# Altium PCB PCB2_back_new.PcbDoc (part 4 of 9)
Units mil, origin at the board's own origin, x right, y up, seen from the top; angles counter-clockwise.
Board outline 6299 x 3937 mil, 4 copper layers (TopLayer, GROUND, VCC, BottomLayer); 253 components, 421 nets, 2085 pads, 712 vias.
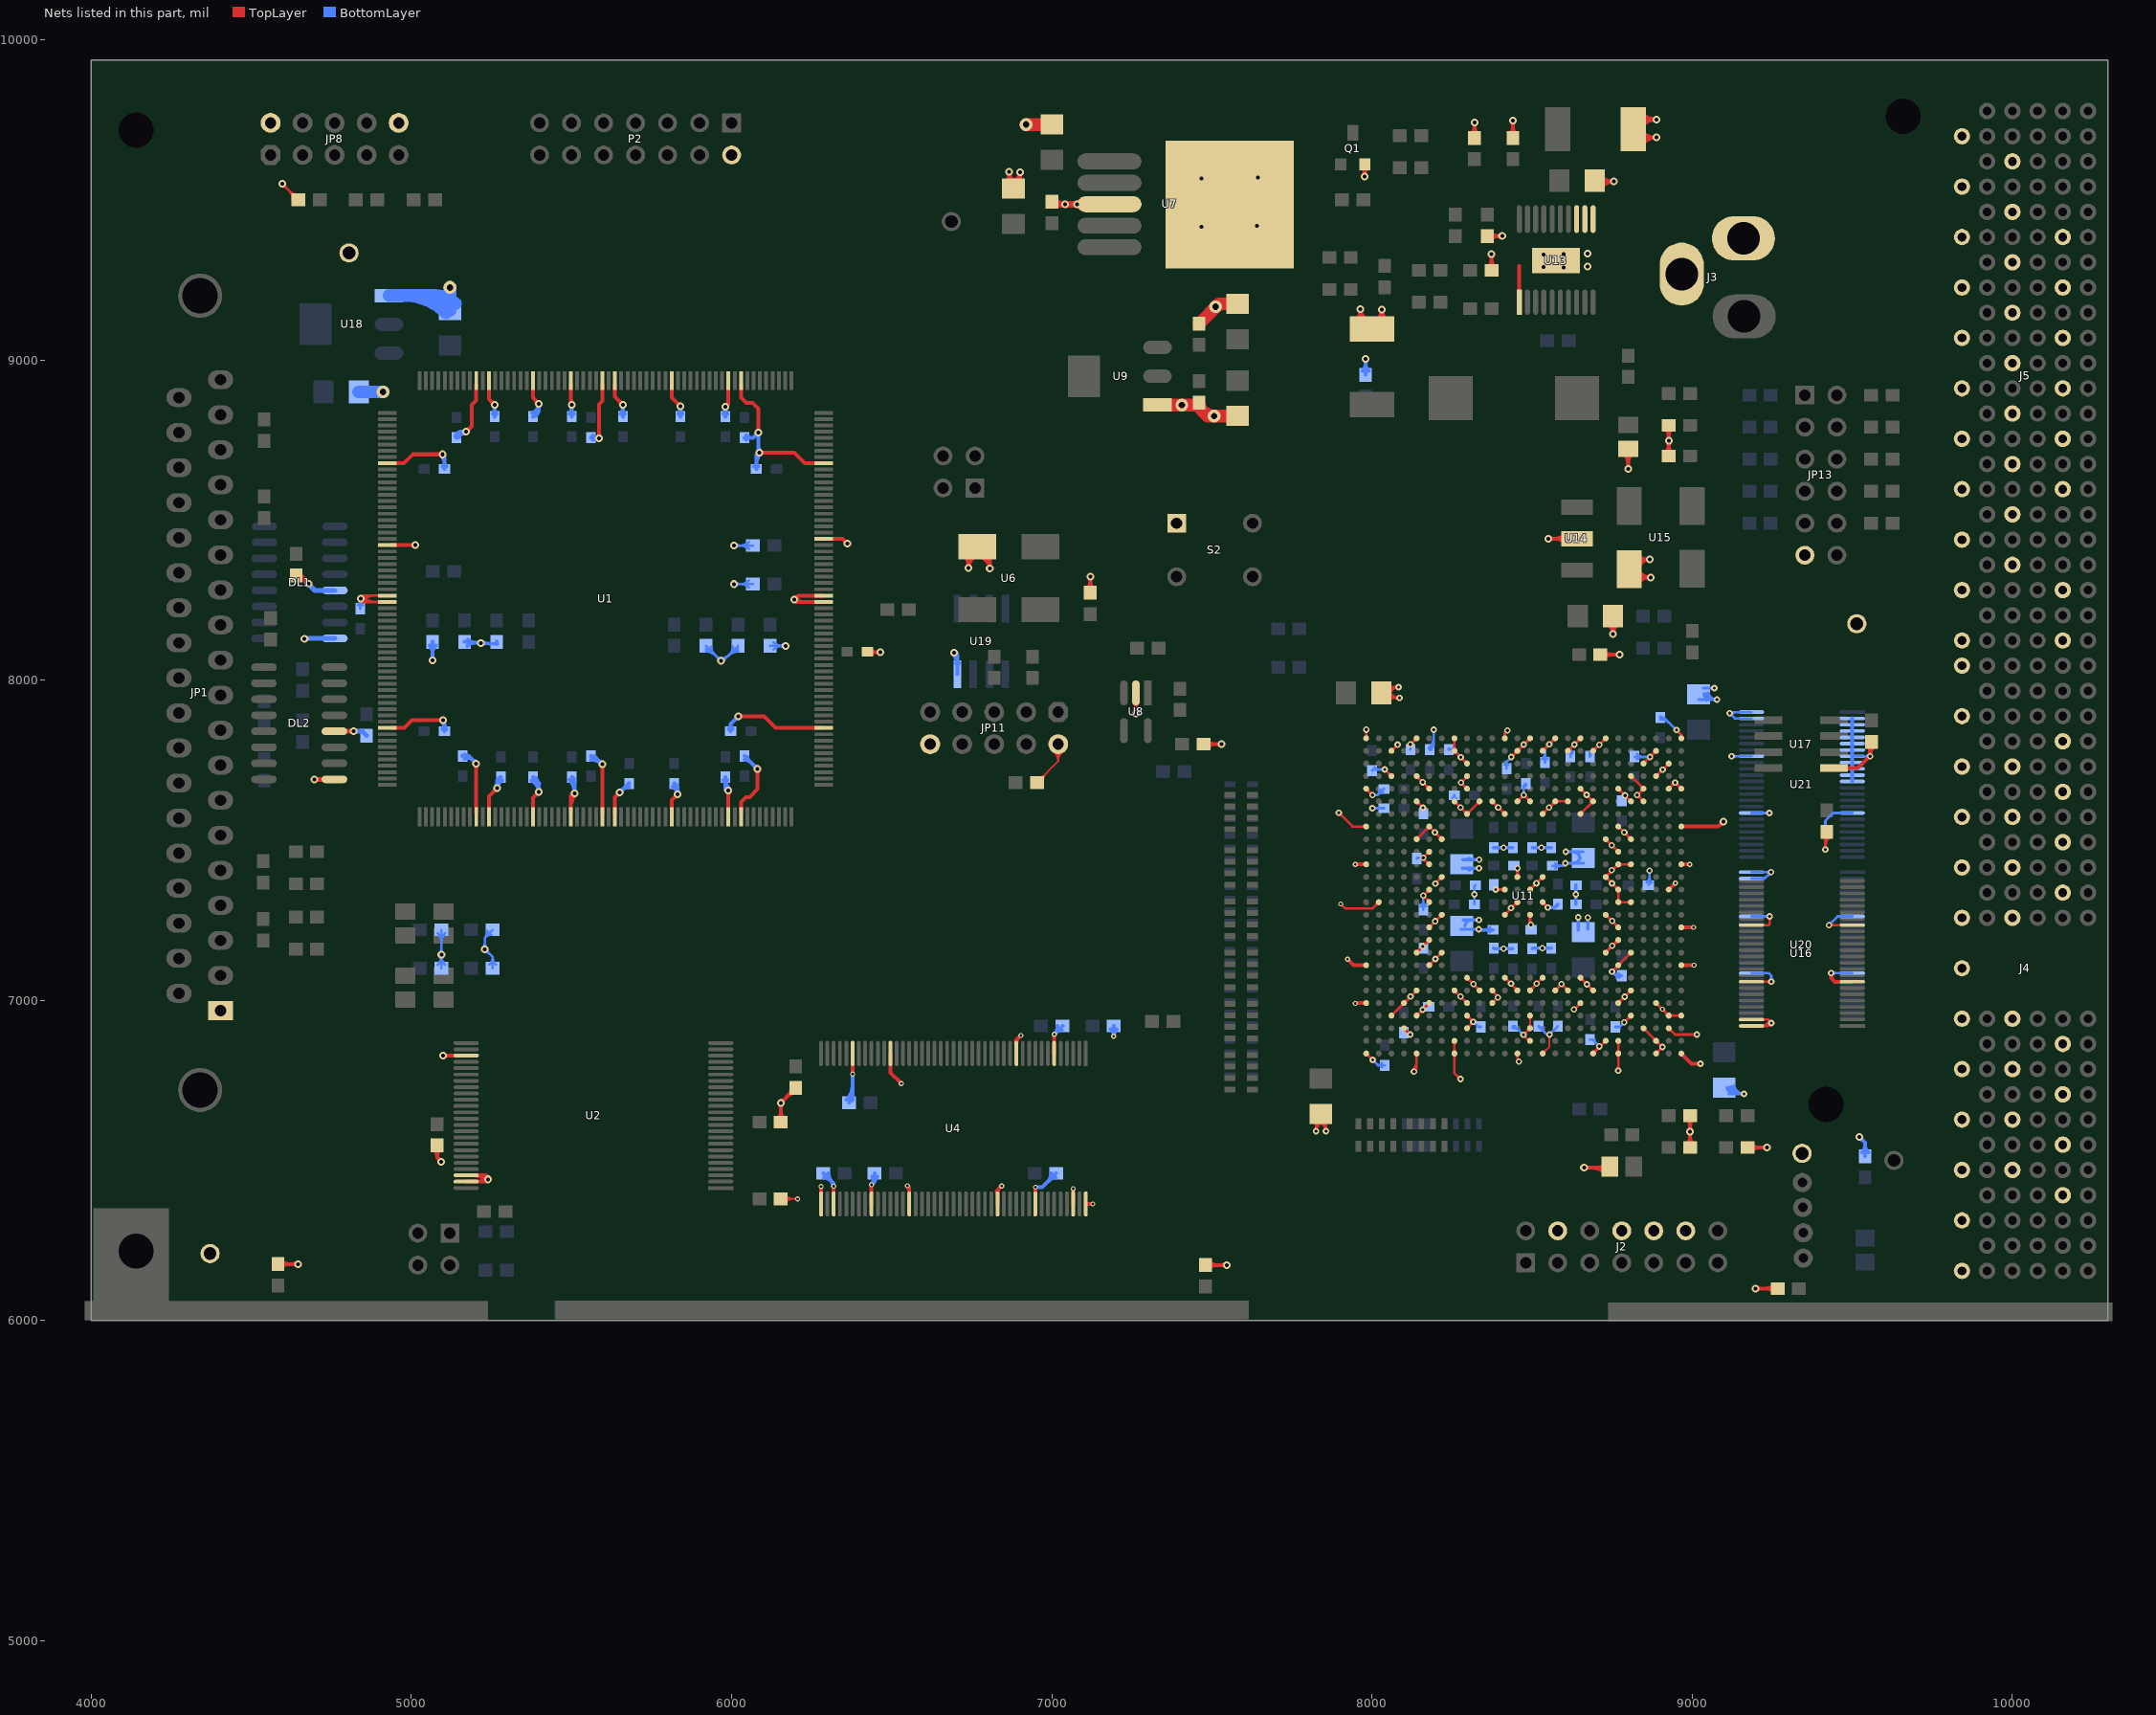
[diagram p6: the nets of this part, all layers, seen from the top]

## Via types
v1: diameter 16, hole 8, TopLayer to BottomLayer, 311 vias
v2: diameter 20, hole 10, TopLayer to BottomLayer, 202 vias
v3: diameter 24, hole 12, TopLayer to BottomLayer, 179 vias
v4: diameter 40, hole 20, TopLayer to BottomLayer, 12 vias
v5: diameter 30, hole 15, TopLayer to BottomLayer, 8 vias

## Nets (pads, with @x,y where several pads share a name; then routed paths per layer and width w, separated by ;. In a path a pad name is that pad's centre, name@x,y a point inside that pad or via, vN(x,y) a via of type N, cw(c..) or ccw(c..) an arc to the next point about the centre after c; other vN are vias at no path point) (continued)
GND: C1.2 C2.2 C5.1 C7.2 C8.1 C10.2 C12.2 C13.2 C14.2 C15.1 C16.1 C17.1 C18.1 C19.1 C20.2 C21.2 C23.2 C27.1 C28.1 C29.2 C30.2 C31.2 C32.1 C33.1 C34.1 C36.1 C37.1 C38.2 C40.2 C42.1 C43.2 C44.2 C45.2 C46.1 C47.2 C48.2 C49.2 C50.2 C51.2 C52.2 C53.2 C54.2 C56.2 C57.2 C58.2 C60.2 C61.2 C63.2 C64.2 C67.2 C68.1 C69.2 C71.2 C72.2 C73.2 C75.2 C76.1 C77.2 C79.1 C80.1 C81.1 C82.1 C83.1 C84.1 C91.2 C92.1 C93.2 C94.2 C95.2 C96.2 C97.2 C98.2 C99.2 C100.2 C101.2 C102.2 C103.2 C104.2 C105.1 C106.2 C107.2 C108.2 C109.2 C110.2 C111.2 C112.1 C113.2 C114.2 C115.2 C116.2 C119.2 C120.2 C121.2 C122.2 C123.2 C124.2 C125.2 C126.2 C127.2 C128.2 C129.2 C130.1 C131.2 C132.2 C133.2 C134.2 C135.2 C136.2 C137.2 C138.2 C139.2 C140.2 C141.2 C142.2 C143.2 C144.2 C145.2 C146.2 C147.2 C148.2 DL1.5 DL1.8 DL2.9 DL2.12 DS4.2 DS5.2 FB1.2 FB3.2 FB5.2 J2.4 J2.8 J2.10 J2.12 J3.2 J3.3 J4.B4 J4.B6 J4.B8 J4.B10 J4.B16 J4.B18 J4.B20 J4.B22 J4.D5 J4.D7 J4.D9 J4.D11 J4.D15 J4.D17 J4.D19 J4.D21 J4.F1 J4.F3 J4.F5 J4.F7 J4.F9 J4.F11 J4.F13 J4.F15 J4.F17 J4.F19 J4.F21 J4.F23 J4.F25 J5.B1 J5.B3 J5.B7 J5.B9 J5.B11 J5.B13 J5.B15 J5.B17 J5.D4 J5.D6 J5.D8 J5.D10 J5.D12 J5.D14 J5.D16 J5.D18 J5.D20 J5.F1 J5.F3 J5.F5 J5.F7 J5.F9 J5.F11 J5.F13 J5.F15 J5.F17 J5.F19 J5.F21 JP1.1 JP8.2 JP8.10 JP11.2 JP11.10 JP13.11 P2.2 pad.5 pad.6 pad.7 pad.8 Q1.3 R4.2 R14.1 R16.2 R17.2 R20.1 R25.1 R48.1 R50.1 R52.1 R53.1 R55.1 R67.1 R68.1 R88.2 R103.2 S2.1 U1.10 U1.30 U1.31 U1.40 U1.52 U1.69 U1.71 U1.80 U1.89 U1.91 U1.96 U1.102 U1.109 U1.111 U1.129 U1.142 U1.150 U1.151 U1.171 U1.190 U1.192 U1.199 U1.205 U1.210 U1.212 U1.221 U1.230 U1.232 U2.27 U2.46 U2.47 U4.6 U4.12 U4.32 U4.38 U4.44 U4.46 U4.52 U4.58 U4.72 U4.78 U4.84 U4.86 U6.2 U7.3 U8.2 U9.1 U11.A1 U11.A3 U11.A6 U11.A8 U11.A12 U11.A14 U11.A19 U11.A22 U11.A26 U11.AA4 U11.AA5 U11.AA8 U11.AA10 U11.AA11 U11.AA13 U11.AA14 U11.AA16 U11.AA17 U11.AA19 U11.AA22 U11.AB1 U11.AB2 U11.AB4 U11.AB6 U11.AB9 U11.AB18 U11.AB21 U11.AB26 U11.AC3 U11.AC5 U11.AC18 U11.AC22 U11.AC24 U11.AD2 U11.AD4 U11.AD18 U11.AE3 U11.AE8 U11.AE10 U11.AE12 U11.AE14 U11.AE19 U11.AE24 U11.AF1 U11.AF7 U11.AF9 U11.AF11 U11.AF13 U11.AF15 U11.AF19 U11.AF22 U11.AF26 U11.B3 U11.B6 U11.B7 U11.B13 U11.B19 U11.C2 U11.C4 U11.C13 U11.C18 U11.C23 U11.D1 U11.D2 U11.D5 U11.D13 U11.D18 U11.D22 U11.D24 U11.E3 U11.E6 U11.E9 U11.E16 U11.E18 U11.E21 U11.E23 U11.E26 U11.F5 U11.F8 U11.F10 U11.F11 U11.F13 U11.F14 U11.F16 U11.F17 U11.F19 U11.F22 U11.G9 U11.G12 U11.G15 U11.G18 U11.H1 U11.H6 U11.H21 U11.H26 U11.J5 U11.J7 U11.J20 U11.J22 U11.K6 U11.K21 U11.L1 U11.L6 U11.L21 U11.M7 U11.M13 U11.M15 U11.M20 U11.N5 U11.N6 U11.N12 U11.N14 U11.N21 U11.N25 U11.P2 U11.P6 U11.P13 U11.P15 U11.P21 U11.R7 U11.R12 U11.R14 U11.R20 U11.T1 U11.T5 U11.T6 U11.T21 U11.T26 U11.U6 U11.U21 U11.V5 U11.V7 U11.V20 U11.V22 U11.W1 U11.W6 U11.W21 U11.W26 U11.Y9 U11.Y12 U11.Y15 U11.Y18 U13.1 U13.11 U13.12 U13.13 U14.2 U15.2 U16.8 U16.17 U16.32 U16.41 U16.47 U16.48 U17.5 U18.1 U19.4 U20.8 U20.17 U20.32 U20.41 U20.47 U20.48 U21.2 U21.3 U21.4 U21.5 U21.6 U21.7 U21.8 U21.9 U21.10 U21.11 U21.12 U21.17 U21.32 U21.41 U21.47 U21.48 | length 33527.3
  TopLayer w6: R20.1@6153.46,6380 v1(6206,6380) ; R20.1@6162.99,6372.44 cw(c6181.23,6354.2) 6181.23,6380 cw(c6181.23,6405.8) R20.1@6162.99,6387.56 ; R20.1@6167.23,6368.2 cw(c6195.71,6339.72) 6195.71,6380 cw(c6195.71,6420.28) R20.1@6167.23,6391.8 ; v1@6202.46,6376.46 ccw(c6193.93,6367.93) 6193.93,6380 ccw(c6193.93,6392.07) v1@6202.46,6383.54 ; R25.1@6953.46,7680 7020,7746.54 ; R25.1@6955.43,7690.69 ccw(c6955.43,7711.73) R25.1@6970.31,7696.85 ; R25.1@6955.43,7696.69 ccw(c6955.43,7732.21) 6980.56,7707.09 ; R25.1@6966.12,7680 cw(c6996.67,7680) 6975.07,7701.6 ; R25.1@6972.12,7680 cw(c7017.15,7680) 6985.31,7711.84 ; JP11.2@7004.05,7776.98 cw(c6982.96,7746.54) 7020,7746.54 ; JP11.2@7007.47,7781.92 cw(c6990.9,7757.99) 7020,7757.99 cw(c7049.1,7757.99) JP11.2@7032.53,7781.92 ; JP11.2@7020,7800 7020,7746.54 ; JP11.2@7035.95,7776.98 ccw(c7057.04,7746.54) 7020,7746.54 ; U11.C13@8489.14,6917.16 ccw(c8478.47,6927.83) 8493.56,6927.83 ccw(c8508.65,6927.83) U11.C13@8497.98,6917.16 ; U11.D13@8489.14,6947.69 cw(c8478.47,6937.02) 8493.56,6937.02 cw(c8508.65,6937.02) U11.D13@8497.98,6947.69 ; U11.C13@8493.56,6912.74 U11.D13@8493.56,6952.11 ; U11.A12@8532.93,6834 8553.99,6855.06 v2(8553.99,6893) ; U11.A12@8532.93,6840.25 ccw(c8532.93,6855.35) 8543.6,6844.67 ccw(c8554.27,6834) U11.A12@8539.18,6834
  TopLayer w8: v3@4596.54,9542 cw(c4596.54,9522.69) 4610.19,9536.34 cw(c4623.85,9550) v3@4604.54,9550 ; v3(4596.54,9550) R14.1@4646.54,9500 ; 4616.4,9530.14 cw(c4586.26,9500) R14.1@4628.88,9500 ; 4621.15,9525.38 ccw(c4644.57,9548.8) R14.1@4644.57,9515.68 ; R14.1@4630.06,9516.48 cw(c4613.58,9500) R14.1@4636.88,9500 ; v3@4836.34,8249.34 ccw(c4848.86,8261.86) 4848.86,8244.16 ; v3@4843.4,8247.12 cw(c4845.28,8236.6) 4852.84,8244.16 ; v3@4844.76,8262.51 ccw(c4846.76,8267.93) 4850.84,8263.84 ; v3@4847.66,8249.34 cw(c4882.66,8214.34) 4882.66,8263.84 ; v3@4847.66,8260.66 ccw(c4887.49,8300.49) 4887.49,8244.16 ; v3@4849.51,8257.76 cw(c4854.93,8259.76) 4850.84,8263.84 ; v3@4849.88,8253.6 ccw(c4860.4,8251.72) 4852.84,8244.16 ; 4863.35,8263.84 ccw(c4863.35,8233.65) v3(4842,8255) ; 4868.18,8244.16 cw(c4868.18,8281.18) v3(4842,8255) ; U1.151@4937.69,8244.16 U1.151@4924.9,8244.16 4852.84,8244.16 ; U1.150@4937.69,8263.84 U1.150@4924.9,8263.84 4850.84,8263.84 ; C20.2@7816.62,6625.44 cw(c7796.39,6605.21) 7825,6605.21 ; v2@7820.76,6595.24 ccw(c7810.51,6605.49) 7825,6605.49 ccw(c7839.49,6605.49) v2@7829.24,6595.24 ; v2@7825,6589.88 cw(c7856.01,6589.88) C20.2@7845.44,6619.03 ; v2(7825,6591) C20.2@7825,6639 ; 7825,6601.29 cw(c7851.87,6601.29) C20.2@7842.71,6626.55 ; 7825,6612.7 cw(c7847.74,6612.7) C20.2@7839.98,6634.07 ; C20.2@7835.09,6618.85 cw(c7825.18,6589.67) v2@7856,6589.67 ; C20.2@7837.67,6626.42 cw(c7828.98,6600.83) v2@7856,6600.83 ; C20.2@7840.24,6634 cw(c7832.77,6612) 7856,6612 ; v2@7851.76,6595.24 ccw(c7841.51,6605.49) 7856,6605.49 ccw(c7870.49,6605.49) v2@7860.24,6595.24 ; v2(7856,6591) C20.2@7856,6644 ; 7856,6607.62 cw(c7881.2,6607.62) C20.2@7863.38,6625.44 ; v2@7896,7580 cw(c7896,7565.51) 7906.24,7575.76 cw(c7916.49,7586) v2@7902,7586 ; v2(7896,7586) 7939.34,7542.66 U11.W26@7981.75,7542.66 ; v1@7902,7297 cw(c7902,7287.34) 7908.83,7294.17 cw(c7915.66,7301) v1@7906,7301 ; v1(7902,7301) 7916,7287 8001.68,7287 U11.N25@8021.12,7306.44 ; U11.W26@7978.03,7538.95 ccw(c7969.07,7529.98) 7969.07,7542.66 ccw(c7969.07,7555.34) U11.W26@7978.03,7546.38 ; U11.AF26@7978.03,7821.97 ccw(c7969.07,7830.93) 7981.75,7830.93 ccw(c7994.43,7830.93) U11.AF26@7985.46,7821.97 ; U11.A26@7981.75,6828.75 cw(c7981.75,6816.07) 7990.71,6825.03 cw(c7999.68,6834) U11.A26@7987,6834 ; U11.A26@7981.75,6834 v2(8002,6813.75) ; U11.AB26@7981.75,7655.52 cw(c7981.75,7642.84) 7990.71,7651.81 cw(c7999.68,7660.77) U11.AB26@7987,7660.77 ; U11.AB26@7981.75,7660.77 v2(8001.52,7641) ; U11.AF26@7981.75,7818.25 v2(7981.75,7845.25) ; U11.N25@8015.87,7306.44 cw(c8003.19,7306.44) 8012.15,7297.48 cw(c8021.12,7288.51) U11.N25@8021.12,7301.19 ; C21.2@8025,7944 v2(8086,7944) cw(c8086,7977.18) C21.2@8054.9,7965.63 ; C21.2@8029,7978 v2(8083,7978) ccw(c8083,7949.79) C21.2@8055.71,7956.95 ; v2(8039.63,7721) U11.AC24@8060.49,7700.14 ; C21.2@8039.9,7960.06 ccw(c8062.99,7968.64) 8062.99,7944 ; C21.2@8040.24,7961.02 cw(c8062.25,7955.24) 8062.25,7978 ; C21.2@8047.4,7962.85 ccw(c8074.5,7972.91) 8074.5,7944 ; C21.2@8047.97,7958.99 cw(c8072.63,7952.51) 8072.63,7978 ; C21.2@8048.56,7936.62 cw(c8066.38,7918.8) 8066.38,7944 ; C21.2@8048.56,7983.38 ccw(c8061.55,7996.37) 8061.55,7978 ; U11.AC24@8055.24,7700.14 ccw(c8042.56,7700.14) 8051.52,7709.11 ccw(c8060.49,7718.07) U11.AC24@8060.49,7705.39 ; U11.D24@8060.49,6952.11 U11.F22@8139.23,7030.85 ; U11.D24@8060.49,6957.36 ccw(c8060.49,6970.04) 8069.45,6961.08 ccw(c8078.42,6952.11) U11.D24@8065.74,6952.11 ; U11.AE24@8060.49,7778.88 v2(8080,7798.39) ; U11.AE24@8060.49,7784.13 ccw(c8060.49,7796.81) 8069.45,7787.85 ccw(c8078.42,7778.88) U11.AE24@8065.74,7778.88 ; v2@8078.76,7973.76 ccw(c8068.51,7963.51) 8068.51,7978 ccw(c8068.51,7992.49) v2@8078.76,7982.24 ; v2@8081.76,7939.76 ccw(c8071.51,7929.51) 8071.51,7944 ccw(c8071.51,7958.49) v2@8081.76,7948.24 ; U11.E23@8094.61,6991.48 cw(c8081.93,6991.48) 8090.89,6982.51 cw(c8099.86,6973.55) U11.E23@8099.86,6986.23 ; U11.C23@8099.86,6907.49 cw(c8099.86,6894.81) 8108.82,6903.77 cw(c8117.79,6912.74) U11.C23@8105.11,6912.74 ; U11.C23@8099.86,6912.74 v2(8119.6,6893) ; U11.E23@8099.86,6996.73 ccw(c8099.86,7009.41) 8108.82,7000.45 ccw(c8117.79,6991.48) U11.E23@8105.11,6991.48 ; v2(8120,7799.02) U11.AF22@8139.23,7818.25 ; v2@8126.76,6781.24 ccw(c8096.65,6811.35) 8139.23,6811.35 ; v2(8131,6777) 8139.23,6785.23 ; v2@8132,6782.92 ccw(c8133.37,6791.08) 8139.23,6785.23 ; v2@8132.41,6775.59 ccw(c8115.96,6792.04) 8139.23,6792.04 ; U11.AF22@8133.98,7818.25 cw(c8121.3,7818.25) 8130.26,7809.29 cw(c8139.23,7800.32) U11.AF22@8139.23,7813 ; U11.A22@8135.51,6830.29 cw(c8126.55,6821.32) 8139.23,6821.32 cw(c8151.91,6821.32) U11.A22@8142.94,6830.29 ; v2@8136.92,6778 cw(c8145.08,6779.37) 8139.23,6785.23 ; U11.A22@8139.23,6834 8139.23,6785.23 ; U11.D22@8139.23,6952.11 U11.E21@8178.6,6991.48 ; U11.D22@8139.23,6957.36 ccw(c8139.23,6970.04) 8148.19,6961.08 ccw(c8157.16,6952.11) U11.D22@8144.48,6952.11 ; U11.J22@8139.23,7148.96 U11.K21@8178.6,7188.33 ; U11.J22@8139.23,7154.21 ccw(c8139.23,7166.89) 8148.19,7157.93 ccw(c8157.16,7148.96) U11.J22@8144.48,7148.96 ; U11.V22@8139.23,7503.29 U11.W21@8178.6,7542.66 U11.V20@8217.97,7503.29 ; U11.V22@8139.23,7508.54 ccw(c8139.23,7521.22) 8148.19,7512.26 ccw(c8157.16,7503.29) U11.V22@8144.48,7503.29 ; U11.AA22@8139.23,7616.15 cw(c8139.23,7603.47) 8148.19,7612.44 cw(c8157.16,7621.4) U11.AA22@8144.48,7621.4 ; U11.AA22@8139.23,7621.4 v2(8159,7601.63) ; U11.AC22@8139.23,7694.89 cw(c8139.23,7682.21) 8148.19,7691.18 cw(c8157.16,7700.14) U11.AC22@8144.48,7700.14 ; U11.AC22@8139.23,7700.14 U11.AB21@8178.6,7660.77 ; 8170,7337 cw(c8178.6,7328.4) U11.P21@8178.6,7340.56 ; 8172.98,7314.02 ccw(c8178.6,7319.64) U11.N21@8178.6,7311.69 ; U11.E21@8173.35,6991.48 cw(c8160.67,6991.48) 8169.63,6982.51 cw(c8178.6,6973.55) U11.E21@8178.6,6986.23 ; U11.K21@8173.35,7188.33 cw(c8160.67,7188.33) 8169.63,7179.37 cw(c8178.6,7170.4) U11.K21@8178.6,7183.08 ; U11.T21@8173.35,7424.55 ccw(c8160.67,7424.55) 8169.63,7433.52 ccw(c8178.6,7442.48) U11.T21@8178.6,7429.8 ; U11.U21@8173.35,7463.92 cw(c8160.67,7463.92) 8169.63,7454.96 cw(c8178.6,7445.99) U11.U21@8178.6,7458.67 ; U11.W21@8173.35,7542.66 cw(c8160.67,7542.66) 8169.63,7533.7 cw(c8178.6,7524.73) U11.W21@8178.6,7537.41 ; U11.AB21@8173.35,7660.77 ccw(c8160.67,7660.77) 8169.63,7669.74 ccw(c8178.6,7678.7) U11.AB21@8178.6,7666.02 ; U11.H21@8178.6,7109.59 U11.J20@8217.97,7148.96 ; U11.H21@8178.6,7114.84 ccw(c8178.6,7127.52) 8187.56,7118.56 ccw(c8196.53,7109.59) U11.H21@8183.85,7109.59 ; U11.L21@8178.6,7227.7 U11.M20@8217.97,7267.07 ; U11.N21@8178.6,7306.44 8178.6,7308.4 v2(8160,7327) 8178.6,7345.6 U11.P21@8178.6,7345.81 ; U11.T21@8178.6,7424.55 8159.68,7443.47 v2(8159.68,7445) U11.U21@8178.6,7463.92 ; v2(8197.79,7365) U11.R20@8217.97,7385.18 ; U11.J20@8212.72,7148.96 cw(c8200.04,7148.96) 8209,7140 cw(c8217.97,7131.03) U11.J20@8217.97,7143.71 ; U11.M20@8212.72,7267.07 cw(c8200.04,7267.07) 8209,7258.11 cw(c8217.97,7249.14) U11.M20@8217.97,7261.82 ; U11.R20@8212.72,7385.18 cw(c8200.04,7385.18) 8209,7376.22 cw(c8217.97,7367.25) U11.R20@8217.97,7379.93 ; U11.V20@8212.72,7503.29 ccw(c8200.04,7503.29) 8209,7512.26 ccw(c8217.97,7521.22) U11.V20@8217.97,7508.54 ; U11.A19@8253.62,6830.29 cw(c8244.66,6821.32) 8257.34,6821.32 cw(c8270.02,6821.32) U11.A19@8261.05,6830.29 ; U11.A19@8253.62,6837.71 ccw(c8244.66,6846.68) 8257.34,6846.68 ccw(c8270.02,6846.68) U11.A19@8261.05,6837.71 ; U11.B19@8253.62,6869.66 cw(c8244.66,6860.69) 8257.34,6860.69 cw(c8270.02,6860.69) U11.B19@8261.05,6869.66 ; U11.AE19@8253.62,7782.6 ccw(c8244.66,7791.56) 8257.34,7791.56 ccw(c8270.02,7791.56) U11.AE19@8261.05,7782.6 ; U11.AF19@8253.62,7814.54 cw(c8244.66,7805.57) 8257.34,7805.57 cw(c8270.02,7805.57) U11.AF19@8261.05,7814.54 ; U11.B19@8257.34,6873.37 8257.34,6772.66 v2(8276,6754) ; U11.F19@8257.34,7025.6 cw(c8257.34,7012.92) 8266.3,7021.88 cw(c8275.27,7030.85) U11.F19@8262.59,7030.85 ; U11.F19@8257.34,7030.85 U11.E18@8296.71,6991.48 ; U11.AA19@8257.34,7616.15 cw(c8257.34,7603.47) 8266.3,7612.44 cw(c8275.27,7621.4) U11.AA19@8262.59,7621.4 ; U11.AA19@8257.34,7621.4 U11.Y18@8296.71,7582.03 U11.AA17@8336.08,7621.4 ; U11.AE19@8257.34,7773.63 cw(c8257.34,7760.95) 8266.3,7769.92 cw(c8275.27,7778.88) U11.AE19@8262.59,7778.88 ; U11.AF19@8257.34,7818.25 U11.AE19@8257.34,7778.88 U11.AD18@8296.71,7739.51 ; v2@8270,6754 ccw(c8255.51,6754) 8265.76,6764.24 ccw(c8276,6774.49) v2@8276,6760 ; 8290.19,7692.19 cw(c8296.71,7685.67) U11.AC18@8296.71,7694.89 ; U11.E18@8291.46,6991.48 ccw(c8278.78,6991.48) 8287.74,7000.45 ccw(c8296.71,7009.41) U11.E18@8296.71,6996.73 ; U11.Y18@8291.46,7582.03 ccw(c8278.78,7582.03) 8287.74,7591 ccw(c8296.71,7599.96) 8296.71,7587.28 ccw(c8296.71,7599.96) 8305.67,7591 ccw(c8314.64,7582.03) U11.Y18@8301.96,7582.03 ; U11.AB18@8291.46,7660.77 ccw(c8278.78,7660.77) 8287.74,7669.74 ccw(c8296.71,7678.7) U11.AB18@8296.71,7666.02 ; U11.AD18@8291.46,7739.51 ccw(c8278.78,7739.51) 8287.74,7748.48 ccw(c8296.71,7757.44) U11.AD18@8296.71,7744.76 ; U11.C18@8296.71,6912.74 8316,6932.03 v2(8316,6932.82) U11.D18@8296.71,6952.11 ; U11.C18@8296.71,6917.99 ccw(c8296.71,6930.67) 8305.67,6921.71 ccw(c8314.64,6912.74) U11.C18@8301.96,6912.74 ; U11.D18@8296.71,6946.86 cw(c8296.71,6934.18) 8305.67,6943.14 cw(c8314.64,6952.11) U11.D18@8301.96,6952.11 ; U11.G18@8296.71,7064.97 cw(c8296.71,7052.29) 8305.67,7061.26 cw(c8314.64,7070.22) U11.G18@8301.96,7070.22 ; U11.G18@8296.71,7070.22 U11.F17@8336.08,7030.85 ; U11.AB18@8296.71,7660.77 8278,7679.48 v2(8278,7680) 8296.71,7698.71 U11.AC18@8296.71,7700.14 ; U11.F17@8330.83,7030.85 ccw(c8318.15,7030.85) 8327.11,7039.82 ccw(c8336.08,7048.78) U11.F17@8336.08,7036.1 ; U11.AA17@8330.83,7621.4 cw(c8318.15,7621.4) 8327.11,7612.44 cw(c8336.08,7603.47) U11.AA17@8336.08,7616.15 ; U11.E16@8375.45,6991.48 v2(8393,7009.03) 8393,7013.3 U11.F16@8375.45,7030.85 ; U11.F16@8375.45,7025.6 cw(c8375.45,7012.92) 8384.41,7021.88 cw(c8393.38,7030.85) U11.F16@8380.7,7030.85 ; U11.AA16@8375.45,7616.15 cw(c8375.45,7603.47) 8384.41,7612.44 cw(c8393.38,7621.4) U11.AA16@8380.7,7621.4 ; U11.AA16@8375.45,7621.4 U11.Y15@8414.82,7582.03 ; U11.Y15@8409.57,7582.03 ccw(c8396.89,7582.03) 8405.85,7591 ccw(c8414.82,7599.96) U11.Y15@8414.82,7587.28 ; U11.AF15@8411.1,7821.97 ccw(c8402.14,7830.93) 8414.82,7830.93 ccw(c8427.5,7830.93) U11.AF15@8418.53,7821.97 ; U11.G15@8414.82,7070.22 U11.F14@8454.19,7030.85 ; U11.M15@8414.82,7267.07 U11.N14@8454.19,7306.44 ; U11.M15@8414.82,7272.32 ccw(c8414.82,7285) 8423.78,7276.04 ccw(c8432.75,7267.07) U11.M15@8420.07,7267.07 ; U11.AF15@8414.82,7818.25 8414.82,7834.82 v2(8423,7843) ; v2(8435,7759.69) v2(8473.88,7798.58) U11.AF13@8493.56,7818.25 ; U11.F14@8448.94,7030.85 ccw(c8436.26,7030.85) 8445.22,7039.82 ccw(c8454.19,7048.78) U11.F14@8454.19,7036.1 ; U11.N14@8448.94,7306.44 cw(c8436.26,7306.44) 8445.22,7297.48 cw(c8454.19,7288.51) U11.N14@8454.19,7301.19 ; U11.AE14@8448.94,7778.88 cw(c8436.26,7778.88) 8445.22,7769.92 cw(c8454.19,7760.95) U11.AE14@8454.19,7773.63 ; U11.A14@8454.19,6834 8454.19,6813.81 v2(8459,6809) ; U11.AA14@8454.19,7621.4 v2(8473.79,7641) 8473.96,7641 U11.AA13@8493.56,7621.4 ; U11.AA14@8454.19,7626.65 ccw(c8454.19,7639.33) 8463.15,7630.37 ccw(c8472.12,7621.4) U11.AA14@8459.44,7621.4 ; U11.AE14@8454.19,7784.13 ccw(c8454.19,7796.81) 8463.15,7787.85 ccw(c8472.12,7778.88) U11.AE14@8459.44,7778.88 ; U11.C13@8488.31,6912.74 cw(c8475.63,6912.74) 8484.59,6903.77 cw(c8493.56,6894.81) U11.C13@8493.56,6907.49 ; U11.AA13@8488.31,7621.4 ccw(c8475.63,7621.4) 8484.59,7630.37 ccw(c8493.56,7639.33) U11.AA13@8493.56,7626.65 ; U11.AF13@8488.31,7818.25 cw(c8475.63,7818.25) 8484.59,7809.29 cw(c8493.56,7800.32) U11.AF13@8493.56,7813 ; U11.B13@8493.56,6873.37 8491.45,6873.37 v2(8472.82,6892) U11.C13@8493.56,6912.74 ; U11.F13@8493.56,7030.85 U11.G12@8532.93,7070.22 ; U11.F13@8493.56,7036.1 ccw(c8493.56,7048.78) 8502.52,7039.82 ccw(c8511.49,7030.85) U11.F13@8498.81,7030.85 ; U11.P13@8493.56,7345.81 U11.R12@8532.93,7385.18 ; U11.P13@8493.56,7351.06 ccw(c8493.56,7363.74) 8502.52,7354.78 ccw(c8511.49,7345.81) U11.P13@8498.81,7345.81 ; U11.R12@8527.68,7385.18 cw(c8515,7385.18) 8523.96,7376.22 cw(c8532.93,7367.25) U11.R12@8532.93,7379.93 ; U11.Y12@8532.93,7582.03 U11.AA11@8572.3,7621.4 U11.AA10@8611.67,7621.4 ; U11.Y12@8532.93,7587.28 ccw(c8532.93,7599.96) 8541.89,7591 ccw(c8550.86,7582.03) U11.Y12@8538.18,7582.03 ; U11.AE12@8532.93,7778.88 U11.AF11@8572.3,7818.25 ; U11.AE12@8532.93,7784.13 ccw(c8532.93,7796.81) 8541.89,7787.85 ccw(c8550.86,7778.88) U11.AE12@8538.18,7778.88 ; U11.AA11@8567.05,7621.4 cw(c8554.37,7621.4) 8563.33,7612.44 cw(c8572.3,7603.47) U11.AA11@8572.3,7616.15 ; U11.AF11@8567.05,7818.25 cw(c8554.37,7818.25) 8563.33,7809.29 cw(c8572.3,7800.32) U11.AF11@8572.3,7813 ; U11.F11@8572.3,7030.85 8591.52,7050.07 v2(8591.52,7051) U11.F10@8611.67,7030.85 ; U11.F11@8572.3,7036.1 ccw(c8572.3,7048.78) 8581.26,7039.82 ccw(c8590.23,7030.85) U11.F11@8577.55,7030.85 ; U11.AA11@8576.01,7617.69 cw(c8584.98,7608.72) 8584.98,7621.4 cw(c8584.98,7634.08) U11.AA11@8576.01,7625.12 ; U11.F10@8606.42,7030.85 ccw(c8593.74,7030.85) 8602.7,7039.82 ccw(c8611.67,7048.78) U11.F10@8611.67,7036.1 ; U11.AA10@8607.96,7617.69 ccw(c8598.99,7608.72) 8598.99,7621.4 ccw(c8598.99,7634.08) U11.AA10@8607.96,7625.12 ; U11.AE10@8611.67,7778.88 U11.AF9@8651.04,7818.25 ; U11.AE10@8611.67,7784.13 ccw(c8611.67,7796.81) 8620.63,7787.85 ccw(c8629.6,7778.88) U11.AE10@8616.92,7778.88 ; v2(8631,6971.44) U11.E9@8651.04,6991.48 ; U11.E9@8645.79,6991.48 cw(c8633.11,6991.48) 8642.07,6982.51 cw(c8651.04,6973.55) U11.E9@8651.04,6986.23 ; U11.AF9@8645.79,7818.25 cw(c8633.11,7818.25) 8642.07,7809.29 cw(c8651.04,7800.32) U11.AF9@8651.04,7813 ; U11.G9@8651.04,7064.97 cw(c8651.04,7052.29) 8660,7061.26 cw(c8668.97,7070.22) U11.G9@8656.29,7070.22 ; U11.G9@8651.04,7070.22 U11.F8@8690.41,7030.85 ; U11.Y9@8651.04,7582.03 U11.AA8@8690.41,7621.4 U11.AB9@8651.04,7660.77 ; U11.Y9@8651.04,7587.28 ccw(c8651.04,7599.96) 8660,7591 ccw(c8668.97,7582.03) U11.Y9@8656.29,7582.03 ; U11.AB9@8651.04,7655.52 cw(c8651.04,7642.84) 8660,7651.81 cw(c8668.97,7660.77) U11.AB9@8656.29,7660.77 ; U11.F8@8685.16,7030.85 ccw(c8672.48,7030.85) 8681.44,7039.82 ccw(c8690.41,7048.78) U11.F8@8690.41,7036.1 ; U11.A8@8690.41,6834 U11.B7@8729.78,6873.37 ; U11.A8@8690.41,6839.25 ccw(c8690.41,6851.93) 8699.37,6842.97 ccw(c8708.34,6834) U11.A8@8695.66,6834 ; U11.AA8@8690.41,7616.15 ccw(c8690.41,7603.47) 8681.44,7612.44 ccw(c8672.48,7621.4) 8685.16,7621.4 ccw(c8672.48,7621.4) 8681.44,7630.37 ccw(c8690.41,7639.33) U11.AA8@8690.41,7626.65 ; U11.AE8@8690.41,7778.88 U11.AF7@8729.78,7818.25 ; U11.AE8@8690.41,7784.13 ccw(c8690.41,7796.81) 8699.37,7787.85 ccw(c8708.34,7778.88) U11.AE8@8695.66,7778.88 ; U11.AF7@8724.53,7818.25 cw(c8711.85,7818.25) 8720.81,7809.29 cw(c8729.78,7800.32) U11.AF7@8729.78,7813 ; U11.M7@8729.78,7261.82 cw(c8729.78,7249.14) 8738.74,7258.11 cw(c8747.71,7267.07) U11.M7@8735.03,7267.07 ; U11.M7@8729.78,7267.07 U11.L6@8769.15,7227.7 ; U11.R7@8729.78,7379.93 cw(c8729.78,7367.25) 8738.75,7376.22 cw(c8747.71,7385.18) 8735.03,7385.18 cw(c8747.71,7385.18) 8738.75,7394.15 cw(c8729.78,7403.11) U11.R7@8729.78,7390.43 ; U11.V7@8729.78,7498.04 cw(c8729.78,7485.36) 8738.74,7494.33 cw(c8747.71,7503.29) U11.V7@8735.03,7503.29 ; U11.V7@8729.78,7503.29 U11.U6@8769.15,7463.92 ; U11.L6@8763.9,7227.7 ccw(c8751.22,7227.7) 8760.18,7236.67 ccw(c8769.15,7245.63) U11.L6@8769.15,7232.95 ; U11.P6@8763.9,7345.81 ccw(c8751.22,7345.81) 8760.18,7354.78 ccw(c8769.15,7363.74) U11.P6@8769.15,7351.06 ; U11.T6@8763.9,7424.55 cw(c8751.22,7424.55) 8760.18,7415.59 cw(c8769.15,7406.62) U11.T6@8769.15,7419.3 ; U11.U6@8763.9,7463.92 ccw(c8751.22,7463.92) 8760.18,7472.89 ccw(c8769.15,7481.85) U11.U6@8769.15,7469.17 ; v2@8764.76,6784.24 ccw(c8754.15,6794.85) 8769.15,6794.85 ; U11.A6@8765.44,6830.29 cw(c8756.47,6821.32) 8769.15,6821.32 cw(c8781.83,6821.32) U11.A6@8772.86,6830.29 ; U11.A6@8765.44,6837.71 ccw(c8756.47,6846.68) 8769.15,6846.68 ccw(c8781.83,6846.68) U11.A6@8772.86,6837.71 ; U11.B6@8765.44,6869.66 cw(c8756.47,6860.69) 8769.15,6860.69 cw(c8781.83,6860.69) U11.B6@8772.86,6869.66 ; U11.N6@8765.44,7310.15 ccw(c8756.47,7319.12) 8769.15,7319.12 ccw(c8781.83,7319.12) 8772.86,7310.15 ccw(c8781.83,7319.12) 8781.83,7306.44 ccw(c8781.83,7293.76) U11.N6@8772.86,7302.73 ; U11.P6@8765.44,7342.1 cw(c8756.47,7333.13) 8769.15,7333.13 cw(c8781.83,7333.13) U11.P6@8772.86,7342.1 ; v2(8769,6780) 8769.15,6780.15 U11.B6@8769.15,6873.37 ; 8769.15,6794.12 ccw(c8783.12,6794.12) v2@8773.24,6784.24 ; U11.E6@8769.15,6991.48 U11.F5@8808.52,7030.85 ; U11.E6@8769.15,6996.73 ccw(c8769.15,7009.41) 8778.12,7000.45 ccw(c8787.08,6991.48) U11.E6@8774.4,6991.48 ; U11.H6@8769.15,7109.59 U11.J5@8808.52,7148.96 ; U11.H6@8769.15,7114.84 ccw(c8769.15,7127.52) 8778.12,7118.56 ccw(c8787.08,7109.59) U11.H6@8774.4,7109.59 ; U11.W6@8769.15,7542.66 U11.V5@8808.52,7503.29 ; U11.AB6@8769.15,7655.52 cw(c8769.15,7642.84) 8778.12,7651.81 cw(c8787.08,7660.77) U11.AB6@8774.4,7660.77 ; U11.AB6@8769.15,7660.77 U11.AA5@8808.52,7621.4 ; U11.T6@8772.86,7420.84 cw(c8781.83,7411.87) 8781.83,7424.55 cw(c8781.83,7437.23) U11.T6@8772.86,7428.27 ; v2(8787.41,6931) U11.D5@8808.52,6952.11 ; U11.D5@8803.27,6952.11 cw(c8790.59,6952.11) 8799.55,6943.14 cw(c8808.52,6934.18) U11.D5@8808.52,6946.86 ; U11.F5@8803.27,7030.85 cw(c8790.59,7030.85) 8799.55,7021.88 cw(c8808.52,7012.92) U11.F5@8808.52,7025.6 ; U11.J5@8803.27,7148.96 cw(c8790.59,7148.96) 8799.55,7140 cw(c8808.52,7131.03) U11.J5@8808.52,7143.71 ; U11.V5@8803.27,7503.29 ccw(c8790.59,7503.29) 8799.55,7512.26 ccw(c8808.52,7521.22) U11.V5@8808.52,7508.54 ; U11.N5@8804.81,7302.73 ccw(c8795.84,7293.76) 8795.84,7306.44 ccw(c8795.84,7319.12) U11.N5@8804.81,7310.15 ; U11.T5@8804.81,7420.84 ccw(c8795.84,7411.87) 8795.84,7424.55 ccw(c8795.84,7437.23) U11.T5@8804.81,7428.27 ; U11.N5@8808.52,7306.44 U11.N6@8769.15,7306.44 U11.P6@8769.15,7345.81 U11.R7@8729.78,7385.18 U11.T6@8769.15,7424.55 U11.T5@8808.52,7424.55 ; U11.AC5@8808.52,7694.89 cw(c8808.52,7682.21) 8817.49,7691.18 cw(c8826.45,7700.14) U11.AC5@8813.77,7700.14 ; U11.AC5@8808.52,7700.14 U11.AB4@8847.89,7660.77 v2(8828.12,7641) 8828,7641 8847.6,7621.4 U11.AA4@8847.89,7621.4 ; 8838.43,7630.57 ccw(c8847.89,7640.04) U11.AA4@8847.89,7626.65 ; 8839.13,7629.87 cw(c8830.66,7621.4) U11.AA4@8842.64,7621.4 ; U11.C4@8847.89,6907.49 cw(c8847.89,6894.81) 8856.86,6903.77 cw(c8865.82,6912.74) U11.C4@8853.14,6912.74 ; U11.C4@8847.89,6912.74 8906.63,6854 v2(8907.26,6854) U11.A3@8887.26,6834 ; U11.AB4@8847.89,7655.52 ccw(c8847.89,7642.84) 8838.92,7651.81 ccw(c8829.96,7660.77) 8842.64,7660.77 ccw(c8829.96,7660.77) 8838.92,7669.74 ccw(c8847.89,7678.7) U11.AB4@8847.89,7666.02 ; U11.AD4@8847.89,7739.51 U11.AE3@8887.26,7778.88 ; U11.AD4@8847.89,7744.76 ccw(c8847.89,7757.44) 8856.86,7748.48 ccw(c8865.82,7739.51) U11.AD4@8853.14,7739.51 ; U11.B3@8882.01,6873.37 ccw(c8869.33,6873.37) 8878.29,6882.34 ccw(c8887.26,6891.3) U11.B3@8887.26,6878.62 ; U11.AE3@8882.01,7778.88 cw(c8869.33,7778.88) 8878.29,7769.92 cw(c8887.26,7760.95) U11.AE3@8887.26,7773.63 ; U11.A3@8887.26,6839.25 ccw(c8887.26,6851.93) 8896.23,6842.97 ccw(c8905.19,6834) U11.A3@8892.51,6834 ; U11.B3@8887.26,6868.12 cw(c8887.26,6855.44) 8896.23,6864.4 cw(c8905.19,6873.37) U11.B3@8892.51,6873.37 ; U11.E3@8887.26,6986.23 cw(c8887.26,6973.55) 8896.23,6982.51 cw(c8905.19,6991.48) U11.E3@8892.51,6991.48 ; U11.E3@8887.26,6991.48 U11.D2@8926.63,6952.11 U11.D1@8966,6952.11 ; U11.AC3@8887.26,7700.14 U11.AD2@8926.63,7739.51 ; U11.AC3@8887.26,7705.39 ccw(c8887.26,7718.07) 8896.23,7709.11 ccw(c8905.19,7700.14) U11.AC3@8892.51,7700.14 ; U11.D2@8921.38,6952.11 ccw(c8908.7,6952.11) 8917.66,6961.08 ccw(c8926.63,6970.04) U11.D2@8926.63,6957.36 ; U11.C2@8926.63,6907.49 cw(c8926.63,6894.81) 8935.6,6903.77 cw(c8944.56,6912.74) U11.C2@8931.88,6912.74 ; U11.C2@8926.63,6912.74 8946.37,6893 v2(9015,6893) ; U11.AB2@8926.63,7660.77 8945.86,7680 v2(8946.77,7680) U11.AB1@8966,7660.77 ; U11.AB2@8926.63,7666.02 ccw(c8926.63,7678.7) 8935.6,7669.74 ccw(c8944.56,7660.77) U11.AB2@8931.88,7660.77 ; U11.D2@8930.34,6948.4 cw(c8939.31,6939.43) 8939.31,6952.11 cw(c8939.31,6964.79) U11.D2@8930.34,6955.82 ; v2(8951,7844) 8966,7829 ; U11.AB1@8960.75,7660.77 ccw(c8948.07,7660.77) 8957.03,7669.74 ccw(c8966,7678.7) U11.AB1@8966,7666.02 ; U11.D1@8962.29,6948.4 ccw(c8953.32,6939.43) 8953.32,6952.11 ccw(c8953.32,6964.79) U11.D1@8962.29,6955.82 ; U11.AF1@8962.77,7822.4 ccw(c8957.63,7829) 8966,7829 ; 8963.09,7831.91 cw(c8949.44,7818.25) U11.AF1@8968.75,7818.25 ; U11.AF1@8966,7818.25 8966,7829 ; U11.AF1@8969.23,7822.4 cw(c8974.37,7829) 8966,7829 ; v2@9010.76,6888.76 ccw(c9000.51,6878.51) 9000.51,6893 ccw(c9000.51,6907.49) v2@9010.76,6897.24 ; U16.48@9185.04,6920 9238,6920 ; U16.47@9185.04,6939.69 9236.32,6939.69 v2(9247,6929) 9238,6920 ; U16.41@9185.04,7057.8 v2(9247.2,7057.8) ; U16.32@9185.04,7234.96 9238.96,7234.96 9242.2,7238.2 v2(9242.2,7262.2) ; U16.48@9210.79,6920 ccw(c9210.79,6965.21) v2@9242.76,6933.24 ; 9230.1,6920 ccw(c9230.1,6945.9) v2@9248.41,6927.59 ; v2@9237.96,7257.96 cw(c9227.72,7247.72) 9242.2,7247.72 cw(c9256.69,7247.72) v2@9246.45,7257.96 ; v2@9241,6929 ccw(c9226.51,6929) 9236.76,6939.24 ccw(c9247,6949.49) v2@9247,6935 ; v2@9241.03,6928.43 cw(c9230.58,6927.42) 9238,6920 ; v2@9242.96,7053.55 ccw(c9232.72,7043.31) 9232.72,7057.8 ccw(c9232.72,7072.28) v2@9242.96,7062.04 ; v2@9246.43,6923.03 ccw(c9245.42,6912.58) 9238,6920 ; C36.1@9408.91,7513.48 cw(c9391.79,7496.36) 9416,7496.36 cw(c9448.21,7496.36) C36.1@9425.43,7519.13 ; v2@9411.76,7475.24 ccw(c9401.51,7485.49) 9416,7485.49 ccw(c9430.49,7485.49) v2@9420.24,7475.24 ; v2(9416,7471) 9416,7522.54 C36.1@9420,7526.54 ; v2@9416,7477.04 cw(c9467.52,7477.04) C36.1@9431.09,7513.48 ; v2(9427.04,7234.96) U16.17@9500,7234.96 ; v2@9431.28,7230.72 cw(c9441.53,7220.47) 9441.53,7234.96 cw(c9441.53,7249.45) v2@9431.28,7239.2 ; v3(4842,8255) 4852.84,8244.16 ; v3(4842,8255) 4850.84,8263.84
  TopLayer w10: v2(8386.19,7345.81) U11.P15@8414.82,7345.81 ; U11.P15@8411.81,7342.8 ccw(c8404.55,7335.55) 8404.55,7345.81 ccw(c8404.55,7356.08) U11.P15@8411.81,7348.82 ; U11.R14@8451.18,7388.19 ccw(c8443.92,7395.45) 8454.19,7395.45 ccw(c8464.45,7395.45) U11.R14@8457.2,7388.19 ; U11.R14@8454.19,7385.18 v2(8454.19,7412.19) ; U11.M13@8490.55,7264.06 cw(c8483.29,7256.81) 8493.56,7256.81 cw(c8503.82,7256.81) U11.M13@8496.57,7264.06 ; U11.M13@8493.56,7267.07 8493.56,7238.44 v2(8496,7236) ; U11.N12@8532.93,7306.44 v2(8549.37,7290) ; U11.J7@8729.78,7148.96 U11.K6@8769.15,7188.33 ; U11.J7@8729.78,7153.21 ccw(c8729.78,7163.48) 8737.04,7156.22 ccw(c8744.3,7148.96) U11.J7@8734.03,7148.96 ; v2(8749.56,7090) U11.H6@8769.15,7109.59 ; U11.H6@8764.9,7109.59 cw(c8754.63,7109.59) 8761.89,7102.33 cw(c8769.15,7095.07) U11.H6@8769.15,7105.34 ; U11.K6@8764.9,7188.33 cw(c8754.63,7188.33) 8761.89,7181.07 cw(c8769.15,7173.81) U11.K6@8769.15,7184.08
  TopLayer w12: FB1.2@4583,6176.46 v3(4645.46,6176.46) ; FB1.2@4592.68,6166.79 cw(c4616.04,6143.43) 4616.04,6176.46 cw(c4616.04,6209.5) FB1.2@4592.68,6186.14 ; v3@4641.22,6172.22 ccw(c4630.98,6161.98) 4630.98,6176.46 ccw(c4630.98,6190.95) v3@4641.22,6180.71 ; U1.171@4937.69,7850.46 4977.46,7850.46 5002,7875 v3(5099,7875) ; U1.142@4937.69,8421.32 v3(5012.32,8421.32) ; U1.129@4937.69,8677.23 4976.23,8677.23 5004,8705 v3(5097,8705) ; v3@5008.08,8417.08 ccw(c4997.84,8406.84) 4997.84,8421.32 ccw(c4997.84,8435.81) v3@5008.08,8425.57 ; C5.1@5070.32,6534.89 cw(c5046.96,6511.53) 5080,6511.53 cw(c5113.04,6511.53) C5.1@5089.68,6534.89 ; C5.1@5080,6546.54 5080,6509 v3(5093,6496) ; v3@5087,6496 ccw(c5072.51,6496) 5082.76,6506.24 ccw(c5093,6516.49) v3@5093,6502 ; v3@5092.76,8700.76 ccw(c5082.51,8690.51) 5082.51,8705 ccw(c5082.51,8719.49) v3@5092.76,8709.24 ; v3@5094.76,7870.76 ccw(c5084.51,7860.51) 5084.51,7875 ccw(c5084.51,7889.49) v3@5094.76,7879.24 ; v3(5098,6827) U2.27@5170.72,6827.39 ; v3@5102.22,6831.27 ccw(c5112.41,6841.56) 5112.49,6827.08 ccw(c5112.56,6812.59) v3@5102.27,6822.78 ; U2.47@5170.72,6433.69 5231.69,6433.69 v3(5239,6441) 5226.63,6453.37 U2.46@5170.72,6453.37 ; v3(5171,8776) 5188,8793 5188,8859 5202.46,8873.46 U1.111@5202.46,8922.31 ; v3@5171,8782 ccw(c5171,8796.49) 5181.24,8786.24 ccw(c5191.49,8776) v3@5177,8776 ; U2.46@5194.65,6453.37 cw(c5194.65,6396.65) v3@5234.76,6436.76 ; v3@5198.21,7735.3 cw(c5187.97,7725.06) 5202.46,7725.06 cw(c5216.94,7725.06) v3@5206.7,7735.3 ; U1.190@5202.46,7585.69 v3(5202.46,7739.54) ; U2.47@5206.85,6433.69 ccw(c5206.85,6473.15) v3@5234.76,6445.24 ; 5223.62,6453.37 cw(c5223.62,6425.62) v3@5243.24,6445.24 ; v3@5233,6441 ccw(c5218.51,6441) 5228.76,6451.24 ccw(c5239,6461.49) v3@5239,6447 ; U1.192@5241.83,7585.69 5241.83,7637.83 v3(5267,7663) ; U1.109@5241.83,8922.31 5241.83,8877.17 v3(5260,8859) ; v3@5254,8859 ccw(c5239.51,8859) 5249.76,8869.24 ccw(c5260,8879.49) v3@5260,8865 ; v3@5261,7663 cw(c5246.51,7663) 5256.76,7652.76 cw(c5267,7642.51) v3@5267,7657 ; U1.199@5379.62,7585.69 5379.62,7632.62 v3(5398,7651) ; U1.102@5379.62,8922.31 5379.62,8881.38 v3@5398,8863 ; 5385.34,8875.66 cw(c5371.69,8862) v3@5391,8862 ; v3@5392,7651 cw(c5377.51,7651) 5387.76,7640.76 cw(c5398,7630.51) v3@5398,7645 ; U1.205@5497.73,7585.69 5497.73,7634.73 v3(5509,7646) ; 5497.73,7604.31 cw(c5550.69,7604.31) v3@5513.24,7641.76 ; 5497.73,7633.28 cw(c5521.72,7633.28) v3@5504.76,7650.24 ; 5497.73,8879.96 ccw(c5519.96,8879.96) v3@5504.24,8864.24 ; U1.96@5497.73,8922.31 5497.73,8862.27 v3(5500,8860) ; v3@5503,7646 cw(c5488.51,7646) 5498.76,7635.76 cw(c5509,7625.51) v3@5509,7640 ; v3@5581.76,8759.24 ccw(c5571.51,8769.49) 5586,8769.49 ccw(c5600.49,8769.49) v3@5590.24,8759.24 ; v3(5586,8755) 5586,8861 5596.16,8871.16 U1.91@5596.16,8922.31 ; v3@5591.91,7732.6 cw(c5581.67,7722.36) 5596.16,7722.36 cw(c5610.64,7722.36) v3@5600.4,7732.6 ; U1.210@5596.16,7585.69 v3(5596.16,7736.84) ; U1.212@5635.53,7585.69 5635.53,7634.53 v3(5650,7649) ; U1.89@5635.53,8922.31 5635.53,8884.47 v3(5660,8860) ; v3@5644,7649 cw(c5629.51,7649) 5639.76,7638.76 cw(c5650,7628.51) v3@5650,7643 ; v3@5654,8860 ccw(c5639.51,8860) 5649.76,8870.24 ccw(c5660,8880.49) v3@5660,8866 ; U1.221@5812.69,7585.69 5812.69,7624.69 v3(5831,7643) ; U1.80@5812.69,8922.31 5812.69,8882.31 v3(5840,8855) ; v3@5825,7643 cw(c5810.51,7643) 5820.76,7632.76 cw(c5831,7622.51) v3@5831,7637 ; v3@5834,8855 ccw(c5819.51,8855) 5829.76,8865.24 ccw(c5840,8875.49) v3@5840,8861 ; v3(5980,8854) 5989.86,8863.86 ; v3@5980.16,8860 ccw(c5980.53,8873.19) 5989.86,8863.86 ; v3@5985.62,7650.9 cw(c5975.37,7640.66) 5989.86,7640.66 cw(c6004.34,7640.66) v3@5994.1,7650.9 ; v3@5986,8854.16 cw(c5999.19,8854.53) 5989.86,8863.86 ; U1.230@5989.86,7585.69 v3(5989.86,7655.14) ; U1.71@5989.86,8922.31 5989.86,8863.86 ; v3(6021,7887) 6101,7887 6137.54,7850.46 U1.10@6287.1,7850.46 ; v3@6025.24,7882.76 cw(c6035.49,7872.51) 6035.49,7887 cw(c6035.49,7901.49) v3@6025.24,7891.24 ; U1.232@6029.23,7585.69 6029.23,7619.23 6045,7635 6057,7635 6081,7659 v3(6081,7721.99) ; U1.69@6029.23,8922.31 6029.23,8882.77 6046,8866 6065,8866 6083,8848 v3(6083,8773) ; v3@6076.76,7717.75 cw(c6066.51,7707.51) 6081,7707.51 cw(c6095.49,7707.51) v3@6085.24,7717.75 ; v3@6078.76,8777.24 ccw(c6068.51,8787.49) 6083,8787.49 ccw(c6097.49,8787.49) v3@6087.24,8777.24 ; v3(6086,8710) 6196,8710 6228.77,8677.23 U1.52@6274.31,8677.23 ; v3@6090.24,8705.76 cw(c6100.49,8695.51) 6100.49,8710 cw(c6100.49,8724.49) v3@6090.24,8714.24 ; C7.2@6143.79,6629.68 ccw(c6120.43,6653.04) 6153.46,6653.04 ccw(c6186.5,6653.04) C7.2@6163.14,6629.68 ; v3@6149.22,6675.76 cw(c6138.98,6665.51) 6153.46,6665.51 cw(c6167.95,6665.51) v3@6157.71,6675.76 ; C7.2@6153.46,6620 v3(6153.46,6680) C8.1@6200,6726.54 ; v3@6153.46,6686 ccw(c6153.46,6700.49) 6163.71,6690.24 ccw(c6173.95,6680) v3@6159.46,6680 ; 6173.28,6699.81 cw(c6200,6673.09) C8.1@6200,6710.88 ; 6178.03,6704.57 ccw(c6158.03,6724.57) C8.1@6186.32,6724.57 ; v3@6196,8257 ccw(c6196,8271.49) 6206.24,8261.24 ccw(c6216.49,8251) v3@6202,8251 ; v3@6200.24,8255.24 ccw(c6227,8282) 6227,8244.16 ; U1.30@6274.31,8244.16 6202.84,8244.16 v3(6196,8251) 6208.84,8263.84 U1.31@6287.1,8263.84 ; U1.40@6274.31,8441.01 6345.99,8441.01 v3(6361,8426) ; U4.44@6279.23,6364 v1(6279.23,6418.23) ; U4.46@6318.6,6364 v1(6318.6,6419.4) ; v3@6355,8426 ccw(c6340.51,8426) 6350.76,8436.24 ccw(c6361,8446.49) v3@6361,8432 ; v1(6377.65,6769.35) U4.38@6377.65,6834 ; C10.2@6422,8087.01 v3(6463.99,8087.01) ; C10.2@6432.86,8081.64 cw(c6445.83,8068.67) 6445.83,8087.01 ; C10.2@6432.86,8094.36 ccw(c6450.61,8112.12) 6450.61,8087.01 ; U4.52@6436.71,6364 v1(6436.71,6423.71) ; v3@6459.75,8082.77 ccw(c6449.51,8072.52) 6449.51,8087.01 ccw(c6449.51,8101.49) v3@6459.75,8091.25 ; U4.32@6495.77,6834 6495.77,6774.23 v1(6530,6740) ; v1@6547.59,6419.59 cw(c6530.12,6402.12) U4.58@6554.82,6402.12 ; v1@6548.9,6419 cw(c6548.58,6412.77) 6554.82,6412.77 ; v1(6549,6421) 6554.82,6415.18 U4.58@6554.82,6364 ; U6.2@6723.72,8393.25 cw(c6684.41,8353.95) v3@6740,8353.95 ; v3@6735.76,8354.24 ccw(c6725.51,8364.49) 6740,8364.49 ccw(c6754.49,8364.49) v3@6744.24,8354.24 ; v3@6740,8349.6 cw(c6782.55,8349.6) U6.2@6762.8,8387.29 ; v3(6740,8350) U6.2@6740,8416 ; 6740,8369.44 cw(c6772.16,8369.44) U6.2@6757.23,8397.92 ; U6.2@6776.8,8384.98 cw(c6764.5,8345.34) v3@6806,8345.34 ; U6.2@6780.35,8396.44 cw(c6769.55,8361.63) 6806,8361.63 ; U6.2@6783.91,8407.9 cw(c6774.61,8377.92) U6.2@6806,8377.92 ; v3@6801.76,8352.24 ccw(c6791.51,8362.49) 6806,8362.49 ccw(c6820.49,8362.49) v3@6810.24,8352.24 ; v3(6806,8348) U6.2@6806,8409 ; U4.72@6830.32,6397.46 cw(c6854.1,6397.46) 6837.28,6414.28 ; U4.72@6830.34,6397.4 cw(c6835.45,6402.37) 6830.41,6407.41 ; U4.72@6830.41,6364 6830.41,6407.41 ; v1(6843,6420) 6830.41,6407.41 ; C12.2@6858.03,9553.15 ccw(c6838.8,9572.38) 6866,9572.38 ; v3@6861.76,9582.76 cw(c6851.51,9572.51) 6866,9572.51 cw(c6880.49,9572.51) v3@6870.24,9582.76 ; C12.2@6866,9536 v3(6866,9587) ccw(c6896.13,9587) C12.2@6885.26,9558.9 ; 6866,9569.49 ccw(c6889.36,9569.49) C12.2@6880.93,9547.71 ; C12.2@6879.43,9560.21 ccw(c6874.8,9586) v3(6901,9586) C12.2@6901,9531 ; C12.2@6881.55,9548.4 ccw(c6877.38,9571.65) 6901,9571.65 ; U4.12@6889.37,6867.46 cw(c6910.87,6867.46) 6895.67,6882.67 ; U4.12@6889.4,6867.4 cw(c6894.03,6871.9) 6889.46,6876.46 ; U4.12@6889.47,6834 6889.47,6876.47 ; v3@6896.76,9581.76 cw(c6886.51,9571.51) 6901,9571.51 cw(c6915.49,9571.51) v3@6905.24,9581.76 ; v1(6903,6890) 6889.47,6876.47 ; U4.78@6948.52,6364 v1(6948.52,6416.52) ; U4.6@7007.57,6834 v1(7007.57,6894.11) ; U4.84@7066.63,6364 v1(7066.63,6411.63) ; U4.86@7106,6364 v1(7128,6364) ; C16.1@7110.32,8285.11 ccw(c7086.96,8308.47) 7120,8308.47 ccw(c7153.04,8308.47) C16.1@7129.68,8285.11 ; v3@7115.76,8318.76 cw(c7105.51,8308.51) 7120,8308.51 cw(c7134.49,8308.51) v3@7124.24,8318.76 ; C16.1@7120,8273.46 v3(7120,8323) ; v3@7258.36,7899.64 ccw(c7248.11,7909.89) 7262.6,7909.89 ccw(c7277.08,7909.89) v3@7266.84,7899.64 ; U8.2@7258.49,7928.33 cw(c7248.57,7918.41) 7262.6,7918.41 cw(c7276.63,7918.41) U8.2@7266.71,7928.33 ; v3(7262.6,7895.4) U8.2@7262.6,7960 ; C19.1@7473.46,7800 v3(7530,7800) ; FB3.2@7480,6173.46 v3(7546.46,6173.46) ; C19.1@7485.11,7790.32 cw(c7508.47,7766.96) 7508.47,7800 cw(c7508.47,7833.04) C19.1@7485.11,7809.68 ; FB3.2@7489.68,6163.79 cw(c7513.04,6140.43) 7513.04,6173.46 cw(c7513.04,6206.5) FB3.2@7489.68,6183.14 ; v3@7525.76,7795.76 ccw(c7515.51,7785.51) 7515.51,7800 ccw(c7515.51,7814.49) v3@7525.76,7804.24 ; v3@7542.22,6169.22 ccw(c7531.98,6158.98) 7531.98,6173.46 ccw(c7531.98,6187.95) v3@7542.22,6177.71 ; v1(7924,7128) 7942.41,7109.59 U11.H26@7981.75,7109.59 ; v1(7947.45,7424.55) U11.T26@7981.75,7424.55 ; C23.2@7947.45,9120.38 ccw(c7910.66,9159) v3(7964,9159) ; v1(7948,6990) 7949.48,6991.48 U11.E26@7981.75,6991.48 ; v3@7959.76,9154.76 cw(c7949.51,9144.51) 7964,9144.51 cw(c7978.49,9144.51) v3@7968.24,9154.76 ; C23.2@7964,9097 v3(7964,9159) ; 7964,9140.09 ccw(c7991.11,9140.09) C23.2@7979.57,9115.56 ; Q1.3@7969.12,9601.52 cw(c7949.12,9581.52) 7977.4,9581.52 cw(c8005.69,9581.52) Q1.3@7985.69,9601.52 ; v3@7973.16,9576.84 ccw(c7962.92,9587.08) 7977.4,9587.08 ccw(c7991.89,9587.08) v3@7981.64,9576.84 ; v3(7977.4,9572.6) Q1.3@7977.4,9610.79 ; C23.2@7984.68,9126.42 cw(c8000.01,9159) v3(7964,9159) ; C23.2@8012.67,9125.02 ccw(c7993.94,9157) v3(8031,9157) ; C23.2@8018.73,9114.66 ccw(c8006.2,9136.07) 8031,9136.07 ; v3@8026.76,9152.76 cw(c8016.51,9142.51) 8031,9142.51 cw(c8045.49,9142.51) v3@8035.24,9152.76 ; C23.2@8031,9101 v3(8031,9157) ; C23.2@8048.48,9123.68 cw(c8071.48,9157) v3(8031,9157) ; C27.1@8310.32,9705.11 ccw(c8286.96,9728.47) 8320,9728.47 ccw(c8353.04,9728.47) C27.1@8329.68,9705.11 ; v3@8315.76,9737.76 cw(c8305.51,9727.51) 8320,9727.51 cw(c8334.49,9727.51) v3@8324.24,9737.76 ; C27.1@8320,9693.46 v3(8320,9742) ; R50.1@8360,9386.54 v3(8406.46,9386.54) ; R48.1@8363.79,9289.68 ccw(c8340.43,9313.04) 8373.46,9313.04 ccw(c8406.5,9313.04) R48.1@8383.14,9289.68 ; v3@8369.22,9326.22 cw(c8358.98,9315.98) 8373.46,9315.98 cw(c8387.95,9315.98) v3@8377.71,9326.22 ; R50.1@8369.68,9376.86 cw(c8393.04,9353.5) 8393.04,9386.54 cw(c8393.04,9419.57) R50.1@8369.68,9396.21 ; R48.1@8373.46,9280 v3(8373.46,9330.46) ; v3@8402.22,9382.29 ccw(c8391.98,9372.05) 8391.98,9386.54 ccw(c8391.98,9401.02) v3@8402.22,9390.78 ; C28.1@8430.32,9705.11 ccw(c8406.96,9728.47) 8440,9728.47 ccw(c8473.04,9728.47) C28.1@8449.68,9705.11 ; v3@8435.76,9742.76 cw(c8425.51,9732.51) 8440,9732.51 cw(c8454.49,9732.51) v3@8444.24,9742.76 ; C28.1@8440,9693.46 v3(8440,9747) ; U13.1@8460,9180 8460,9293 ; v3(8550.57,8441.57) U14.2@8640,8441.57 ; v3@8554.82,8437.33 cw(c8565.06,8427.09) 8565.06,8441.57 cw(c8565.06,8456.06) v3@8554.82,8445.82 ; U14.2@8601.95,8429.11 ccw(c8571.87,8399.03) 8571.87,8441.57 ccw(c8571.87,8484.12) U14.2@8601.95,8454.04 ; v3(8662,6477) DS4.2@8743.6,6478 ; v3@8666.19,6481.29 ccw(c8676.31,6491.66) 8676.48,6477.18 ccw(c8676.66,6462.69) v3@8666.29,6472.81 ; 8685.86,6477.29 cw(c8686.6,6416.71) DS4.2@8728.92,6460.07 ; C30.2@8695,9557 v3(8756,9557) ccw(c8756,9499.17) C30.2@8713.75,9538.66 ; 8704.66,6477.52 ccw(c8704.24,6511.52) DS4.2@8728.58,6487.78 ; C30.2@8704.98,9546.85 cw(c8728.36,9525) 8728.36,9557 ; C30.2@8713.15,9574.09 ccw(c8754.41,9615.35) v3@8754.41,9557 ; C32.1@8713.46,8080 v3(8774,8080) ; 8714.83,6477.65 cw(c8715.22,6446.03) DS4.2@8737.3,6468.66 ; C32.1@8725.11,8070.32 cw(c8748.47,8046.96) 8748.47,8080 cw(c8748.47,8113.04) C32.1@8725.11,8089.68 ; C29.2@8736.93,8176.11 cw(c8710.75,8143.2) v3(8752.8,8143.2) ; v3@8748.56,8147.44 ccw(c8738.32,8157.68) 8752.8,8157.68 ccw(c8767.29,8157.68) v3@8757.05,8147.44 ; v3@8751.76,9552.76 ccw(c8741.51,9542.51) 8741.51,9557 ccw(c8741.51,9571.49) v3@8751.76,9561.24 ; C29.2@8752.8,8200 v3(8752.8,8143.2) ; C29.2@8768.68,8176.11 ccw(c8794.86,8143.2) v3(8752.8,8143.2) ; v3@8769.76,8075.76 ccw(c8759.51,8065.51) 8759.51,8080 ccw(c8759.51,8094.49) v3@8769.76,8084.24 ; DS5.2@8786.15,8708.74 cw(c8752.7,8675.3) 8800,8675.3 cw(c8847.3,8675.3) DS5.2@8813.85,8708.74 ; v3@8795.76,8664.24 ccw(c8785.51,8674.49) 8800,8674.49 ccw(c8814.49,8674.49) v3@8804.24,8664.24 ; v3(8800,8660) DS5.2@8800,8722.6 ; U15.2@8802,8320 v3(8870,8320) cw(c8870,8361.89) U15.2@8832.79,8342.65 ; U15.2@8813,8377 v3(8868,8377) ccw(c8868,8340.4) U15.2@8834.08,8354.15 ; C31.2@8819,9695 v3(8889,9695) ccw(c8889,9639.54) C31.2@8843.56,9671.34 ; C31.2@8819,9751 v3(8889,9751) ; U15.2@8822.13,8337.13 ccw(c8850.28,8351.69) 8850.28,8320 ; U15.2@8822.95,8358.66 cw(c8850.18,8347.62) 8850.18,8377 ; U15.2@8826.75,8303.72 cw(c8866.05,8264.41) v3@8866.05,8320 ; U15.2@8826.75,8390.28 ccw(c8858.81,8422.34) v3@8858.81,8377 ; C31.2@8831.33,9705.58 ccw(c8856.88,9731.13) 8856.88,9695 ; C31.2@8831.93,9764.01 ccw(c8861.62,9791.37) 8861.62,9751 ; C31.2@8832.87,9736.13 cw(c8863.93,9711.12) 8863.93,9751 ; C31.2@8833.73,9678.22 cw(c8865.95,9655.67) 8865.95,9695 ; C31.2@8839.82,9714.07 ccw(c8885.85,9760.1) v3@8885.85,9695 ; C31.2@8840.76,9772.14 ccw(c8889,9816.6) v3(8889,9751) ; C31.2@8842.22,9728.6 cw(c8889,9690.95) v3(8889,9751) ; v3@8863.76,8372.76 ccw(c8853.51,8362.51) 8853.51,8377 ccw(c8853.51,8391.49) v3@8863.76,8381.24 ; v3@8865.76,8315.76 ccw(c8855.51,8305.51) 8855.51,8320 ccw(c8855.51,8334.49) v3@8865.76,8324.24 ; v3@8884.76,9690.76 ccw(c8874.51,9680.51) 8874.51,9695 ccw(c8874.51,9709.49) v3@8884.76,9699.24 ; v3@8884.76,9746.76 ccw(c8874.51,9736.51) 8874.51,9751 ccw(c8874.51,9765.49) v3@8884.76,9755.24 ; C33.1@8916.86,8709.68 ccw(c8893.5,8733.04) 8926.54,8733.04 ccw(c8959.57,8733.04) C33.1@8936.21,8709.68 ; C34.1@8916.86,8785.32 cw(c8893.5,8761.96) 8926.54,8761.96 cw(c8959.57,8761.96) C34.1@8936.21,8785.32 ; v3@8922.29,8742.76 cw(c8912.05,8732.51) 8926.54,8732.51 cw(c8941.02,8732.51) v3@8930.78,8742.76 ; v3@8922.29,8751.24 ccw(c8912.05,8761.49) 8926.54,8761.49 ccw(c8941.02,8761.49) v3@8930.78,8751.24 ; C33.1@8926.54,8695 C34.1@8926.54,8795 ; U11.P2@8926.63,7345.81 v1(8947,7366) ; U11.A1@8966,6834 8998,6802 v2(9026,6802) ; U11.H1@8966,7109.59 v1(9005.59,7109.59) ; U11.L1@8966,7227.7 v1(9004.3,7227.7) ; U11.T1@8966,7424.55 v1(8992.55,7424.55) ; U11.W1@8966,7542.66 9081.66,7542.66 v3(9097,7558) ; R52.1@8983.79,6549.68 ccw(c8960.43,6573.04) 8993.46,6573.04 ccw(c9026.5,6573.04) R52.1@9003.14,6549.68 ; R53.1@8983.79,6630.32 cw(c8960.43,6606.96) 8993.46,6606.96 cw(c9026.5,6606.96) R53.1@9003.14,6630.32 ; v3@8989.22,6585.76 cw(c8978.98,6575.51) 8993.46,6575.51 cw(c9007.95,6575.51) v3@8997.71,6585.76 ; v3@8989.22,6594.24 ccw(c8978.98,6604.49) 8993.46,6604.49 ccw(c9007.95,6604.49) v3@8997.71,6594.24 ; R52.1@8993.46,6540 R53.1@8993.46,6640 ; v3@9091,7558 cw(c9076.51,7558) 9086.76,7547.76 cw(c9097,7537.51) v3@9097,7552 ; R55.1@9173.46,6540 v3(9234,6540) ; R55.1@9185.11,6530.32 cw(c9208.47,6506.96) 9208.47,6540 cw(c9208.47,6573.04) R55.1@9185.11,6549.68 ; v3(9198,6100) FB5.2@9266.54,6100 ; v3@9202.24,6095.76 cw(c9212.49,6085.51) 9212.49,6100 cw(c9212.49,6114.49) v3@9202.24,6104.24 ; v3@9229.76,6535.76 ccw(c9219.51,6525.51) 9219.51,6540 ccw(c9219.51,6554.49) v3@9229.76,6544.24 ; FB5.2@9254.89,6090.32 ccw(c9231.53,6066.96) 9231.53,6100 ccw(c9231.53,6133.04) FB5.2@9254.89,6109.68 ; v2(9434.04,7085.04) 9434.04,7069.76 9446,7057.8 U16.8@9500,7057.8 ; v2@9437.22,7082.61 ccw(c9447.59,7074.67) 9438.36,7065.44 ; U17.5@9442.36,7725 9518,7725 v2(9555.2,7762.2) 9555.2,7801.74 C37.1@9560,7806.54 ; U17.5@9477.97,7720.89 cw(c9487.89,7710.97) 9487.89,7725 cw(c9487.89,7739.03) U17.5@9477.97,7729.11 ; C37.1@9550.32,7794.89 cw(c9538.54,7783.1) 9555.2,7783.1 ; v2@9555.2,7761.94 cw(c9599.93,7761.94) C37.1@9569.36,7794.58
  TopLayer w15: C2.2@4640,8326.54 4653.46,8326.54 v3(4679,8301) ; v3(4696,7690.1) DL2.9@4759.3,7690.1 ; DL2.12@4759.3,7840.1 4818.9,7840.1 v3(4819,7840)
  TopLayer w20: C15.1@7000,9493.46 7007.46,9486 U7.3@7180,9486 ; C15.1@7006.85,9498.34 ccw(c7036.65,9528.15) v3@7036.65,9486 ; U7.3@7094.39,9475.39 ccw(c7068.79,9449.79) 7068.79,9486 ccw(c7068.79,9522.21) U7.3@7094.39,9496.61
  TopLayer w40: v4(6919.88,9735.12) C148.2@7000,9735.12 ; U9.1@7330,8859 7452.46,8859 7486.58,8824.88 C13.2@7580,8824.88 ; C17.1@7459.69,8864.57 ccw(c7490.56,8864.57) 7468.73,8842.74 ; C18.1@7460,9113.46 7521.65,9175.12 C14.2@7580,9175.12 ; 7472.15,8839.32 ccw(c7507,8874.17) v4(7507,8824.88) ; v4(7511,9166) cw(c7533.01,9143.99) 7533.01,9175.12
  BottomLayer w6: C142.2@8862.99,7360 C142.2@8867,7364.01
